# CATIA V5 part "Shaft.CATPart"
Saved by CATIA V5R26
Part number: Part2
Material "Iron": density 7870 kg/m3, Young's modulus 2.11e+11 Pa, Poisson ratio 0.291, thermal expansion 1.21e-05 1/K
Bounding box of the stored display mesh (mm): x -20.121 to 20.121, y 0 to 300, z -20.121 to 20.121
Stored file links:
  D:\_Deepak\CATIA\New Chapter\C19 FEA\Tutorial\TUT02\Shaft.CATPart
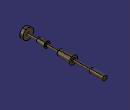
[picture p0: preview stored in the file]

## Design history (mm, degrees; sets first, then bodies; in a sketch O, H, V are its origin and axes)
Body1 (main body), material "Iron"
  Sketch1 on yz-plane, origin (0, 0, 0), H (0, 1, 0), V (0, 0, 1)
    line L1 (0, 0) -> (0, 20.127)
    line L2 (0, 20.127) -> (12.0221, 20.127)
    line L3 (12.0221, 20.127) -> (12.0221, 5.2746)
    point P3 (12.0221, 5.2746)
    line L4 (12.0221, 5.2746) -> (51.1457, 5.2746)
    line L5 (51.1457, 5.2746) -> (51.1457, 8.5349)
    line L6 (51.1457, 8.5349) -> (82.0221, 11.1079)
    line L7 (82.0221, 11.1079) -> (82.0221, 5.2746)
    point P7 (82.0221, 5.2746)
    line L8 (82.0221, 5.2746) -> (132.0221, 5.2746)
    line L9 (132.0221, 5.2746) -> (132.0221, 10.9839)
    line L10 (132.0221, 10.9839) -> (182.0221, 15.1506)
    line L11 (182.0221, 15.1506) -> (182.0221, 5.2746)
    point P11 (182.0221, 5.2746)
    line L12 (182.0221, 5.2746) -> (250, 5.2746)
    line L13 (250, 5.2746) -> (250, 8.5349)
    line L14 (250, 8.5349) -> (300, 8.5349)
    line L15 (300, 8.5349) -> (300, 0)
    point P15 (300, 0)
    axis line L16 (0, 0) -> (300, 0)
    distance L15 L1 = 300
    distance L13 L1 = 250
    distance L11 L7 = 100
    distance L3 L7 = 70
    distance L9 L11 = 50
    vertical: L1 V, L3 V, L5 V, L7 V, L9 V, L11 V, L13 V, L15 V
    horizontal: L2 H, L4 H, L8 H, L12 H, L14 H, L16 H
    coincidence: L6 P3, P7 L4, P11 L4, P15 H
    parallelism: L10 L6
  Shaft1: profile Sketch1, axis Sketch1.L16, angle 360
  Fillet1: radius 2, on edge [face of Shaft1 from Sketch1.L7 | face of Shaft1 from Sketch1.L8]; edge [face of Shaft1 from Sketch1.L4 | face of Shaft1 from Sketch1.L5]; edge [face of Shaft1 from Sketch1.L8 | face of Shaft1 from Sketch1.L9]; edge [face of Shaft1 from Sketch1.L11 | face of Shaft1 from Sketch1.L12]; edge [face of Shaft1 from Sketch1.L12 | face of Shaft1 from Sketch1.L13]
